// Mitsubishi GX Works2 project: 实例训练（红绿灯）   PLC: FX3U/FX3UC

PROGRAM MAIN
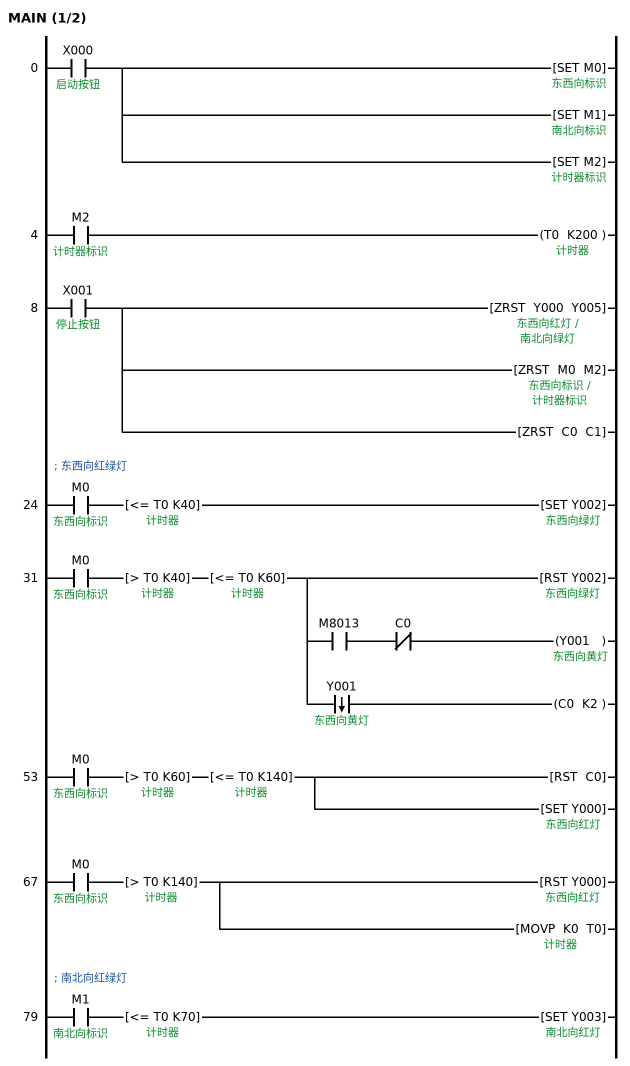
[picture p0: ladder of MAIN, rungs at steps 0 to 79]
0     LD      X000  ; 启动按钮
      SET     M0  ; 东西向标识
      SET     M1  ; 南北向标识
      SET     M2  ; 计时器标识
4     LD      M2  ; 计时器标识
      OUT     T0 K200  ; 计时器
8     LD      X001  ; 停止按钮
      ZRST    Y000 Y005  ; 东西向红灯 / 南北向绿灯
      ZRST    M0 M2
      ZRST    C0 C1
; 东西向红绿灯
24    LD      M0  ; 东西向标识
      AND<=   T0 K40  ; 计时器
      SET     Y002  ; 东西向绿灯
31    LD      M0  ; 东西向标识
      AND>    T0 K40  ; 计时器
      AND<=   T0 K60  ; 计时器
      RST     Y002  ; 东西向绿灯
      MPS
      AND     M8013
      ANI     C0
      OUT     Y001  ; 东西向黄灯
      MPP
      ANDF    Y001  ; 东西向黄灯
      OUT     C0 K2
53    LD      M0  ; 东西向标识
      AND>    T0 K60  ; 计时器
      AND<=   T0 K140  ; 计时器
      RST     C0
      SET     Y000  ; 东西向红灯
67    LD      M0  ; 东西向标识
      AND>    T0 K140  ; 计时器
      RST     Y000  ; 东西向红灯
      MOVP    K0 T0
; 南北向红绿灯
79    LD      M1  ; 南北向标识
      AND<=   T0 K70  ; 计时器
      SET     Y003  ; 南北向红灯
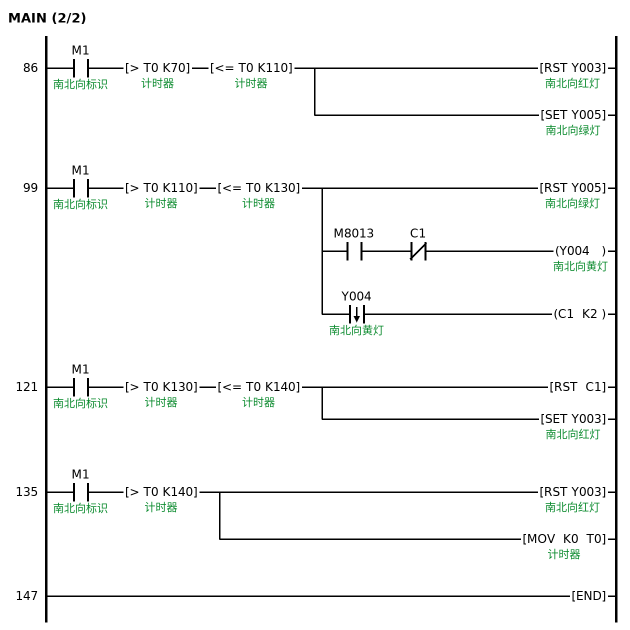
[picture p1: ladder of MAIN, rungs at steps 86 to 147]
86    LD      M1  ; 南北向标识
      AND>    T0 K70  ; 计时器
      AND<=   T0 K110  ; 计时器
      RST     Y003  ; 南北向红灯
      SET     Y005  ; 南北向绿灯
99    LD      M1  ; 南北向标识
      AND>    T0 K110  ; 计时器
      AND<=   T0 K130  ; 计时器
      RST     Y005  ; 南北向绿灯
      MPS
      AND     M8013
      ANI     C1
      OUT     Y004  ; 南北向黄灯
      MPP
      ANDF    Y004  ; 南北向黄灯
      OUT     C1 K2
121   LD      M1  ; 南北向标识
      AND>    T0 K130  ; 计时器
      AND<=   T0 K140  ; 计时器
      RST     C1
      SET     Y003  ; 南北向红灯
135   LD      M1  ; 南北向标识
      AND>    T0 K140  ; 计时器
      RST     Y003  ; 南北向红灯
      MOV     K0 T0
147   END
END_PROGRAM

// device comments not shown above
T1  ; 闪烁
D0  ; 时间系数
